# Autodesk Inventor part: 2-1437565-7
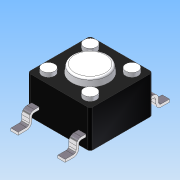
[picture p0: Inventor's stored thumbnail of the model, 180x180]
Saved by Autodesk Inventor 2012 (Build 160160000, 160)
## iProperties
Created: 2009-09
Part Number: 2-1437565-7
Document SubType Name: Modeling
Designer: CaDesign UK Ltd
Density: 1.06 g/cm^3
Material: ABS Plastic
Description: Tyco - Push Button Switch
Mass: 0.146776 g
Surface Area: 1.89125 cm^2
Volume: 0.138468 cm^3
Title: Tyco - Push Button Switch
Author: CaDesign UK Ltd
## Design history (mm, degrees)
sketch "Sketch1"
  geometry: L1 (-2.75, -3)-(2.75, -3); L2 (3, -2.75)-(3, 2.75); L3 (2.75, 3)-(-2.75, 3); L4 (-3, 2.75)-(-3, -2.75); A1 r 0.25 centre (-2.75, 2.75) between (-2.75, 3) and (-3, 2.75); A2 r 0.25 centre (2.75, 2.75) between (3, 2.75) and (2.75, 3); A3 r 0.25 centre (2.75, -2.75) between (2.75, -3) and (3, -2.75); A4 r 0.25 centre (-2.75, -2.75) between (-3, -2.75) and (-2.75, -3); 4 further points
  constraints: 8 end point, 8 point on circle, 8 tangent, 6 point on line, 4 centre point, 3 equal radius, 2 parallel, 1 horizontal, 1 perpendicular
  dimensions: "d0" = 6 distance of point (-3, 3) point (-3, -3); "d1" = 6 distance of point (-3, -3) point (3, -3); "d2" = 3 distance from line of L4 point (0, 0) (= 0.5 x d1); "d3" = 3 distance from line of L3 point (0, 0) (= 0.5 x d0); "d4" = 0.25 radius of A1
extrude "Extrusion1" new body sketch "Sketch1" distance "d5" = 3.57; taper "d6" = 0 deg
workplane "Work Plane1"
sketch "Sketch2"
  geometry: L1 (0, 5.75)-(-3.57, 5.75) reference; L2 (-1, 5.75)-(-1, 6.2); L3 (-0.75, 6.45)-(-0.4, 6.45); L4 (0.1, 6.95)-(0.1, 7.75); L5 (0.1, 7.75)-(-0.15, 7.75); L6 (-0.15, 7.75)-(-0.15, 6.95); L7 (-0.4, 6.7)-(-0.75, 6.7); L8 (-1.25, 6.2)-(-1.25, 5.75); L9 (0, 5.75)-(0, 5.5) reference; A1 r 0.25 centre (-0.4, 6.95) between (-0.4, 6.7) and (-0.15, 6.95); A2 r 0.25 centre (-0.75, 6.2) between (-0.75, 6.45) and (-1, 6.2); A3 r 0.5 centre (-0.75, 6.2) between (-0.75, 6.7) and (-1.25, 6.2); A4 r 0.5 centre (-0.4, 6.95) between (-0.4, 6.45) and (0.1, 6.95); 1 further point
  constraints: 14 end point, 8 point on circle, 8 tangent, 5 parallel, 4 centre point, 2 equal radius, 2 perpendicular, 2 point on line
  dimensions: "d8" = 0.25 distance between parallel lines of L4 L6; "d9" = 0.1 distance between parallel lines of L9 L4; "d10" = 0.25 distance between parallel lines of L3 L7; "d11" = 2 distance between parallel lines of L5 L1; "d12" = 0.7 distance between parallel lines of L3 L1; "d13" = 0.25 distance between parallel lines of L2 L8; "d14" = 1 distance between parallel lines of L2 L9; "d15" = 0.25 radius of A1; "d16" = 0.5 radius of A3
extrude "Extrusion2" join sketch "Sketch2" stored distance "d17" = 0.7; taper "d18" = 0 deg
mirror "Mirror1"
mirror "Mirror2"
sketch "Sketch3"
  geometry: C1 r 0.6 at (-2, 2); 1 further point
  constraints: 1 centre point
  dimensions: "d19" = 2 horizontal distance of C1.centre point (0, 0); "d20" = 2 horizontal distance of C1.centre point (0, 0); "d21" = 1.2 diameter of C1
extrude "Extrusion3" join sketch "Sketch3" distance "d22" = 0.4; taper "d23" = 0 deg
mirror "Mirror3"
mirror "Mirror4"
sketch "Sketch4"
  geometry: C1 r 1.75 at (0, 0); 1 further point
  constraints: 1 centre point, 1 coincident
  dimensions: "d24" = 3.5 diameter of C1
workplane "Work Plane2"
sketch "Sketch5"
  geometry: C1 r 1.65 at (0, 0); 1 further point
  constraints: 1 centre point, 1 coincident
  dimensions: "d26" = 3.3 diameter of C1
loft "Loft1" sketch "Sketch5" dims "d27" = 0, "d28" = 90 deg, "d29" = 0, "d30" = 90 deg
fillet "Fillet1" dims "d31" = 0.2
body "Solid1"
other parameters: "d7" = -0.75, "d25" = 0.71
